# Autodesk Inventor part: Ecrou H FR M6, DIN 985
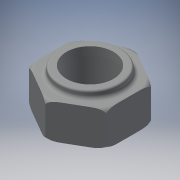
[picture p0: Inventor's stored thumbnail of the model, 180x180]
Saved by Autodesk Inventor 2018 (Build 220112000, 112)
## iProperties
Created: 2007-09
Part Number: Ecrou H FR M6, DIN 985
Document SubType Name: Modeling
Designer: Administrateur
Material: Générique
Density: 1 g/cm^3
Appearance: Style de couleur converti
Author: Administrateur
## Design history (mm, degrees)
feature "Base1"
node "Solide1"
node "Corps solides"
node "Corps surfaciques"
